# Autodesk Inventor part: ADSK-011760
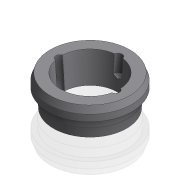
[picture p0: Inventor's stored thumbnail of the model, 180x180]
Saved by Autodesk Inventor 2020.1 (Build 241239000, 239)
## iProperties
Created: 2000-02
Part Number: ADSK-011760
Material: RA HRS
Description: HUB,WELD-ON,TAPER BUSHED
Document SubType Name: Modeling
Designer: glanglot
Density: 7.83 g/cm^3
Appearance: Métal - Acier
Mass: 1703.19 g
Surface Area: 402.367 cm^2
Volume: 217.521 cm^3
Control State: 0
Checked Out: False
Master: False
Shininess: 0.0
Length Units: 11269
Angle Units: 11279
Time Units: 11290
Mass Units: 11283
Length Display Precision: 3
Angle Display Precision: 2
Compacted: True
Material Desc: HUB,WELD-ON,TAPER BUSHED
Material_Number: A103262
Dimensions: 124x44,5x124 mm
Mass: 1,703 kg
Density: 0.0
Volumn: 0.0
Area: 0.0
PropertySet Name: Model Information
Author: glanglot
Revision Number: -
Title: HUB,WELD-ON,TAPER BUSHED
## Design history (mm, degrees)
node "Revolution1" dims "d11" = 90 deg
  sketch "Sketch1"
    geometry: L1 (-74.4, 0)-(12.4, 0) reference; L2 (-54, 0)-(-55, 13); L3 (-55, 13)-(-55, 25.5); L4 (-55, 25.5)-(-62, 25.5); L5 (-62, 25.5)-(-62, 35); L6 (-62, 35)-(-58.729, 44.5); L7 (-58.729, 44.5)-(-43, 44.5); L8 (-43, 44.5)-(-39.888, 0); L9 (-54, 0)-(-39.888, 0); L10 (0, 53.4)-(0, -8.9) reference; 1 further point
    constraints: 16 end point, 4 perpendicular, 2 point on line, 1 parallel
    dimensions: "d2" = 55 distance between parallel lines of L10 L3 (= 0.5 x G); "d3" = 54 distance from line of L10 L2.start (= 0.5 x H); "d4" = 86 deg angle of L1 L8 (computed from TAPER); "d7" = 44.5 distance between parallel lines of L7 L1 (= B); "d8" = 9.5 distance from line of L7 L5.end (= F); "d9" = 19 distance between parallel lines of L4 L7 (= D); "d10" = 12.5 distance from line of L2.end L4 (= C); "d27" = 86 diameter of L7.end L10 (= J_REF); "d28" = 124 diameter of L5 L10 (= A); "d29" = 19 deg angle of L6 L5
sketch "Sketch2"
  geometry: L1 (86.8, 0)-(-86.8, 0) reference; L2 (0, 0)-(41.093, -3.595); L3 (0, 0)-(-41.093, -3.595); L4 (0, 0)-(0, 41.25); C1 r 58.729 at (0, 0) reference; A1 r 41.25 centre (0, 0) between (41.093, -3.595) and (-41.093, -3.595); 3 further points
  constraints: 6 end point, 4 coincident, 3 point on circle, 1 centre point, 1 perpendicular
  dimensions: "d12" = 82.5 diameter of A1 (= BC); "d13" = 5 deg angle of L3 L1; "d14" = 5 deg angle of L1 L2
node "Hole1" dims "d15" = 12, "d16" = 9.525, "d17" = 6.35, "d18" = 60 deg, "d19" = 32.3, "d20" = 118 deg, "d30" = 24
node "Hole2" dims "d21" = 10.2, "d22" = 9.525, "d23" = 6.35, "d24" = 60 deg, "d25" = 25, "d26" = 118 deg, "d31" = 6
node "Solide1"
node "Corps solides"
node "Corps surfaciques"
other parameters: "A" = 124 [user parameter; used in 1 equation term], "B" = 44.5 [user parameter; used in 1 equation term], "C" = 12.5 [user parameter; used in 1 equation term], "D" = 19 [user parameter; used in 1 equation term], "F" = 9.5 [user parameter; used in 1 equation term], "H" = 108 [user parameter; used in 1 equation term], "J_REF" = 86 [user parameter; used in 1 equation term], "K_1" = 117.5 [user parameter], "L" = 41 [user parameter], "M" = 57 [user parameter], "N_1" = 44.5 [user parameter], "TAPER" = 8 deg [user parameter; used in 1 equation term], "BC" = 82.5 [user parameter; used in 1 equation term]
